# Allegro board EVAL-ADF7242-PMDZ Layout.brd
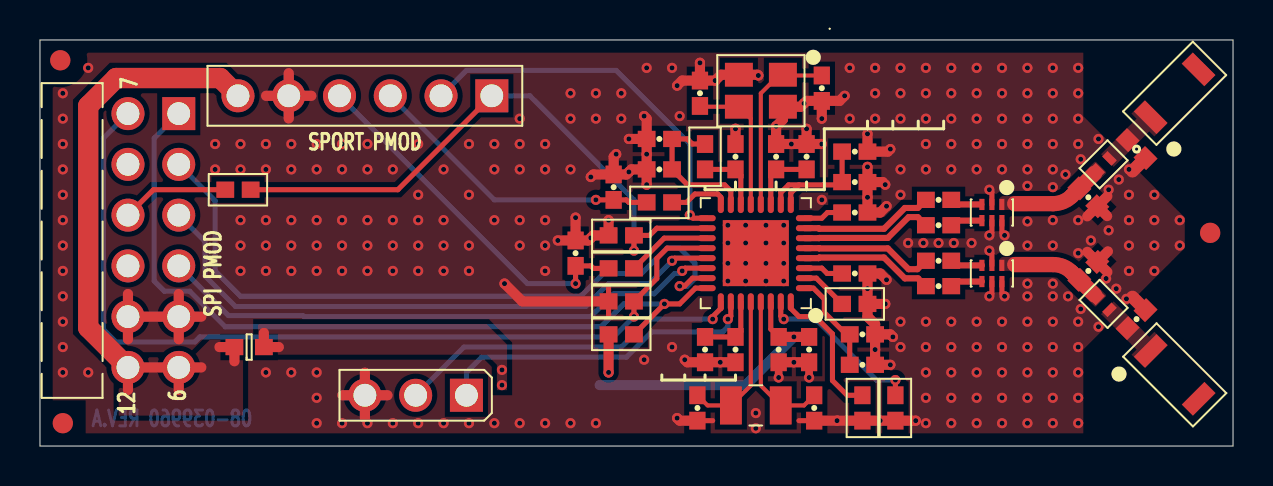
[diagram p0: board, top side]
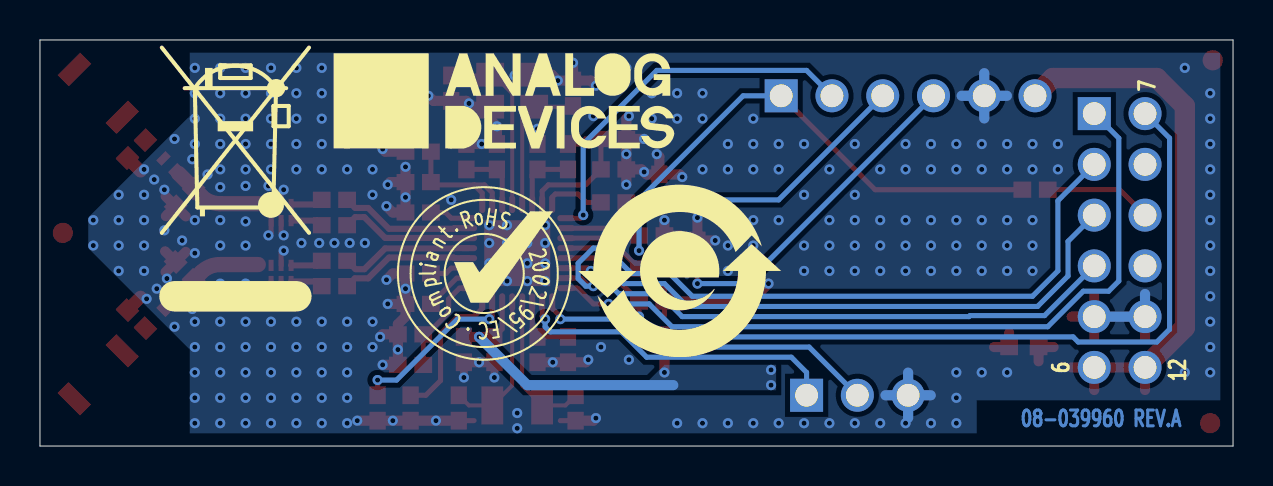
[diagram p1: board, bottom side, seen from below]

Outline 59.69 x 20.32 mm; copper layers: TOP, L2_GND, L3_GND, BOTTOM. Coordinates in mm from the lower left corner of the outline.
Outline path: 0,20.32 0,0 59.69,0 59.69,20.32 0,20.32

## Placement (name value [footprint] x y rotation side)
C1  0.22uF  [C0402]  41.15 4.06 180 top
C2  27pF  [C0402]  41.15 5.59 180 top
C3  27pF  [C0402]  40.77 8.64 180 top
C4  10000pF  [C0402]  44.96 8 180 top
C5  0.1UF  [C0402]  28.7 12.95 270 top
C6  10000pF  [C0402]  44.96 9.27 180 top
C7  10000pF  [C0402]  44.96 11.05 180 top
C8  10000pF  [C0402]  44.96 12.32 180 top
C9  0.1UF  [C0402]  26.8 9.65 270 top
C10  18pF  [C0402]  39.12 17.91 90 top
C11  1pF  [C0402]  54.86 14.86 135 top
C12  27pF  [C0402]  40.77 11.68 180 top
C13  27pF  [C0402]  34.8 4.83 270 top
C14  27pF  [C0402]  40.77 13.21 180 top
C15  0.22uF  [C0402]  40.77 14.73 180 top
C16  1pF  [C0402]  54.86 6.35 225 top
C17  27pF  [C0402]  36.83 14.48 270 top
C18  0.22uF  [C0402]  38.35 14.48 270 top
C19  1pF  [C0402]  52.45 12.45 135 top
C20  18pF  [C0402]  33.02 17.65 270 top
C21  27pF  [C0402]  34.8 14.48 270 top
C22  0.1UF  [C0402]  30.99 15.37 0 top
C23  27pF  [C0402]  30.99 13.84 0 top
C24  0.1UF  [C0402]  36.96 4.83 90 top
C25  27pF  [C0402]  38.48 4.83 90 top
C26  8pF  [C0402]  38.73 1.91 90 top
C27  8pF  [C0402]  32.89 1.91 90 top
C28  0.1UF  [C0402]  33.27 4.83 270 top
C29  1pF  [C0402]  52.45 8.76 225 top
E1  600OHMS  [L0603]  10.46 4.95 0 top
FL1  2400-2500MEGHZ  [FLSML126W63H55]  56.77 3.56 315 top
FL2  2400-2500MEGHZ  [FLSML126W63H55]  56.77 17.65 45 top
L1  2.4nH  [L0402-2]  53.21 7.11 135 top
L2  2.4nH  [L0402-2]  53.21 14.1 225 top
NOREF  -  []  -219.71 -146.05 0 top
NOREF#2  -  []  119.38 340.74 0 top
NOREF#3  -  []  32.59 36.5 0 top
NOREF#4  -  [unnamed#2]  1.14 1.14 0 top
NOREF#5  -  []  0 0 0 top
NOREF#6  -  []  0 20.32 270 top
NOREF#7  -  []  161.8 51.82 0 top
NOREF#8  -  []  1.14 1.14 0 top
NOREF#9  -  []  0 20.32 0 top
NOREF#10  -  []  -88.27 331.85 0 top
NOREF#11  -  []  33.76 58.18 0 top
NOREF#12  -  [unnamed#2]  58.55 10.67 0 top
NOREF#13  -  []  0 20.32 0 top
NOREF#14  -  []  -219.71 -146.05 0 top
NOREF#15  -  []  -219.71 -146.05 0 top
NOREF#16  -  []  0 0 0 top
NOREF#17  -  []  59.69 20.32 180 top
NOREF#18  -  []  59.69 0 90 top
NOREF#19  -  []  0 0 0 top
NOREF#20  -  []  1.14 1.14 0 top
NOREF#21  -  []  59.69 0 90 top
NOREF#22  -  [unnamed#2]  1.02 19.3 0 top
NOREF#23  -  []  59.69 0 0 top
NOREF#24  -  []  36.45 17.27 180 bottom
NOREF#25  -  []  27.69 8.76 180 bottom
NOREF#26  -  []  37.47 8.64 180 bottom
NOREF#27  -  []  40.64 23.62 180 bottom
P1  TSW-106-25-F-D-RA  [CNHDRRA2X6H240]  6.94 16.63 270 top
P2  TSW-106-09-G-S  [CNHDR1X6H330]  22.61 17.53 180 top
P3  MOLEX22-03-2031  [CNMOLEX22-03-2031]  21.34 2.54 180 top
R1  100K  [R0402]  42.8 1.91 90 top
R2  100K  [R0402]  41.15 1.91 90 top
R3  27K  [R0402]  40.77 7.11 180 top
R4  0  [R0402]  33.27 14.48 90 top
R5  100K  [R0402]  29.08 5.59 180 top
R6  0  [R0402]  9.91 12.83 0 top
R7  100K  [R0402]  29.08 7.24 0 top
R8  100K  [R0402]  29.08 10.54 0 top
R9  0  [R0402]  29.08 8.89 180 top
R10  0  [R0402]  30.99 12.19 180 top
U1  ADF7242BCPZ  [QFN32_5X5_PAD3_3X3_3]  35.81 9.65 90 top
U2  2400-2500MEGHZ  [FL0603-6P]  47.62 11.68 180 top
U3  2400-2500MEGHZ  [FL0603-6P]  47.62 8.64 180 top
Y1  26.000MEGHZ  [XTALNX3225]  36.07 17.78 180 top
Y2  32.768KHz  [YSML126W59H35]  35.81 2.03 180 top

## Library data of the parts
C1 C15 C18 = CAP: Tolerance: 10; User Part Number: UPN; alternate symbols: (C0402H22_ALT,C0201-2,C0402_A,C0402_ALT,C0402L_ALT,C0603L_ALT); part number: CAP_SM-0.22UF,10V,10,E011012,C0402; tolerance: 10
C2 C3 C12-C14 C17 C21 C23 C25 = CAP: Tolerance: 5; User Part Number: UPN; alternate symbols: (C0402H22_ALT,C0201-2,C0402_A,C0402_ALT,C0402L_ALT,C0603L_ALT); part number: CAP_SM-27PF,50V,5,E006647,C0402; tolerance: 5
C4 C6-C8 = CAP: Tolerance: 10; User Part Number: UPN; alternate symbols: (C0402H22_ALT,C0201-2,C0402_A,C0402_ALT,C0402L_ALT,C0603L_ALT); part number: CAP_SM-10000PF,50V,10,E021852,C0402; tolerance: 10
C5 C9 C22 C24 C28 = CAP: Tolerance: 10; User Part Number: UPN; alternate symbols: (C0402H22_ALT,C0201-2,C0402_A,C0402_ALT,C0402L_ALT,C0603L_ALT); part number: CAP_SM-0.1UF,16V,10,E007200,C0402; tolerance: 10
C10 C20 = CAP: Tolerance: 5; User Part Number: UPN; alternate symbols: (C0402H22_ALT,C0201-2,C0402_A,C0402_ALT,C0402L_ALT,C0603L_ALT); part number: CAP_SM-18PF,50V,5,E007476,C0402; tolerance: 5
C11 C16 C19 C29 = CAP: Tolerance: 0.25pF; User Part Number: UPN; alternate symbols: (C0402H22_ALT,C0201-2,C0402_A,C0402_ALT,C0402L_ALT,C0603L_ALT); part number: CAP_SM-1PF,50V,0.25PF,E022519,C0402; tolerance: 0.25pF
C26 C27 = CAP: Tolerance: +/-0.5pF; User Part Number: UPN; alternate symbols: (C0402H22_ALT,C0201-2,C0402_A,C0402_ALT,C0402L_ALT,C0603L_ALT); part number: CAP_SM-8PF,50V,+/-0.5PF,E012604,C0402; tolerance: +/-0.5pF
E1 = FERRITE: Tolerance: N/A; User Part Number: UPN; alternate symbols: (L1210H59_ALT); part number: FERRITE_SM-600OHMS,N/A,E007179,L0603; tolerance: N/A
FL1 FL2 = FLTRRF2P: User Part Number: UPN; part number: FLTRRF2P_SM-2400-2500MEGHZ,E021871,FLSML126W63H55
L1 L2 = IND: Tolerance: 2; User Part Number: UPN; alternate symbols: (L0402-2,L0603_ALT,L1008L_ALT); part number: IND_SM-2.4NH,2,E020887,L0402-2; tolerance: 2
P1 = CN12P_V3: User Part Number: UPN; part number: CN12P_V3_TH-TSW-106-25-F-D-RA,E018495,CNHDRRA2X6H240
P2 = CN6P: User Part Number: UPN; part number: CN6P_TH-TSW-106-09-G-S,E020774,CNHDR1X6H330
P3 = CN3P: User Part Number: UPN; part number: CN3P_TH-MOLEX22-03-2031,E000811,CNMOLEX22-03-2031
R1 R2 R5 R7 R8 = RES: Tolerance: 1; User Part Number: UPN; alternate symbols: (RRAD984L1500W75H520LD32;TO220H590_ALT;R0402_A;R0603_A,R0402_ALT,R0402L_ALT); part number: RES_SM-100K,E003796,1/16W,1,R0402; tolerance: 1
R3 = RES: Tolerance: 1; User Part Number: UPN; alternate symbols: (RRAD984L1500W75H520LD32;TO220H590_ALT;R0402_A;R0603_A,R0402_ALT,R0402L_ALT); part number: RES_SM-27K,E007442,1/16W,1,R0402; tolerance: 1
R4 R6 R9 R10 = RES: Tolerance: 1; User Part Number: UPN; alternate symbols: (RRAD984L1500W75H520LD32;TO220H590_ALT;R0402_A;R0603_A,R0402_ALT,R0402L_ALT); part number: RES_SM-0,E010661,1/16W,1,R0402; tolerance: 1
U1 = ADF7242: User Part Number: UPN; part number: ADF7242_SM-ADF7242BCPZ,E020886,QFN32_5X5_PAD3_3X3_3
U2 U3 = FLTRBALUN6P: User Part Number: UPN; part number: FLTRBALUN6P_SM-2400-2500MEGHZ,E020950,FL0603-6P
Y1 = XTALNX3225: User Part Number: UPN; part number: XTALNX3225_SM-26.000MEGHZ,E014734,XTALNX3225
Y2 = XTAL: User Part Number: UPN; Tolerance: 20PPM; part number: XTAL_SM-32.768KHZ,E019185,YSML126W59H35; tolerance: 20PPM

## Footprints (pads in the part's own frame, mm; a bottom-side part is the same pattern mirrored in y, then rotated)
C0402
  rect 0.889x0.813 smd: 1(-0.635,0) 2(0.635,0)
CNHDR1X6H330
  rect 1.651x1.651 hole 1.143: 1(0,0)
  round 1.651 hole 1.143: 2(2.54,0) 3(5.08,0) 4(7.62,0) 5(10.16,0) 6(12.7,0)
CNHDRRA2X6H240
  rect 1.651x1.651 hole 1.143: 1(0,0)
  round 1.651 hole 1.143: 2(2.54,0) 3(5.08,0) 4(7.62,0) 5(10.16,0) 6(12.7,0) 7(0,-2.54) 8(2.54,-2.54) 9(5.08,-2.54) 10(7.62,-2.54) 11(10.16,-2.54) 12(12.7,-2.54)
CNMOLEX22-03-2031
  rect 1.651x1.651 hole 1.143: 1(0,0)
  round 1.651 hole 1.143: 2(2.54,0) 3(5.08,0)
FL0603-6P
  rect 0.254x0.559 smd: 1(-0.5,-0.404) 2(0,-0.404) 3(0.5,-0.404) 4(0.5,0.404) 5(0,0.404) 6(-0.5,0.404)
FLSML126W63H55
  rect 0.787x1.6 smd: 1(-1.694,0) 2(1.694,0)
L0402-2
  rect 0.381x0.66 smd: 1(-0.419,0) 2(0.419,0)
L0603
  rect 0.889x0.813 smd: 1(-0.737,0) 2(0.737,0)
QFN32_5X5_PAD3_3X3_3
  oval 0.305x0.889 smd: 1(-1.75,-2.45) 2(-1.25,-2.45) 3(-0.75,-2.45) 4(-0.25,-2.45) 5(0.25,-2.45) 6(0.75,-2.45) 7(1.25,-2.45) 8(1.75,-2.45) 17(1.75,2.45) 18(1.25,2.45) 19(0.75,2.45) 20(0.25,2.45) 21(-0.25,2.45) 22(-0.75,2.45) 23(-1.25,2.45) 24(-1.75,2.45)
  oval 0.889x0.305 smd: 9(2.45,-1.75) 10(2.45,-1.25) 11(2.45,-0.75) 12(2.45,-0.25) 13(2.45,0.25) 14(2.45,0.75) 15(2.45,1.25) 16(2.45,1.75) 25(-2.45,1.75) 26(-2.45,1.25) 27(-2.45,0.75) 28(-2.45,0.25) 29(-2.45,-0.25) 30(-2.45,-0.75) 31(-2.45,-1.25) 32(-2.45,-1.75)
  rect 3.302x3.302 smd: PAD(0,0)
R0402
  rect 0.889x0.813 smd: 1(-0.635,0) 2(0.635,0)
unnamed#2
  round 1.016 smd: (0,0)
XTALNX3225
  rect 1.397x1.194 smd: 1(-1.1,-0.8) 2(1.1,-0.8) 3(1.1,0.8) 4(-1.1,0.8)
YSML126W59H35
  rect 1.092x1.905 smd: 1(-1.246,0) 2(1.246,0)

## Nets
DGND: C1.1(N1) C2.1(N1) C3.1(N1) C5.1(N1) C9.1(N1) C10.1(N1) C11.1(N1) C12.1(N1) C13.2(N2) C14.1(N1) C15.1(N1) C16.1(N1) C17.1(N1) C18.1(N1) C19.1(N1) C20.1(N1) C21.1(N1) C22.1(N1) C23.1(N1) C24.1(N1) C25.1(N1) C26.1(N1) C27.1(N1) C28.2(N2) C29.1(N1) P1.5(GND1) P1.11(GND2) P2.5(N5) P3.3(N3) R1.1(N1) R2.1(N1) R3.1(N1) R7.1(N1) R8.1(N1) U1.PAD(EPAD) U2.2(GND1) U2.5(GND2) U2.6(GND3) U3.2(GND1) U3.5(GND2) U3.6(GND3) Y1.2(CASE1) Y1.4(CASE2)
DVDD: E1.1(N1) P1.6(VCC1) P1.12(VCC2) P2.6(N6)
CS: P1.1(P1) R5.1(N1) U1.24(CS_N)
DR: C5.2(N2) P2.3(N3) R10.2(N2)
DT: P2.2(N2) U1.17(DT_GP1)
IRQ1IN: P1.7(P7) R7.2(N2) U1.20(IRQ1_GP4)
IRQ2_TRFS: P2.1(N1) R6.2(N2) R8.2(N2) U1.18(IRQ2_TRFS_GP2)
MISO: P1.3(P3) U1.21(MISO)
MOSI: P1.2(P2) U1.23(MOSI)
RFVDD: C24.2(N2) C25.2(N2) E1.2(N2) R5.2(N2) U1.30(VDD_BAT)
RXEN: P3.1(N1) U1.26(RXEN_GP6)
SCLK: P1.4(P4) U1.22(SCLK)
SPORT_CLK: C9.2(N2) P2.4(N4) R9.2(N2)
TXEN: P3.2(N2) U1.25(TXEN_GP5)
UNNAMED_4_ADF7242_I75_CREGDIG1: C13.1(N1) C28.1(N1) U1.27(CREGDIG1)
UNNAMED_4_ADF7242_I75_CREGDIG2: C22.2(N2) C23.2(N2) R4.2(N2) U1.15(CREGDIG2)
UNNAMED_4_ADF7242_I75_CREGRF1: C1.2(N2) C2.2(N2) U1.1(CREGRF1)
UNNAMED_4_ADF7242_I75_CREGRF2: C3.2(N2) U1.3(CREGRF2)
UNNAMED_4_ADF7242_I75_CREGRF3: C12.2(N2) U1.8(CREGRF3)
UNNAMED_4_ADF7242_I75_CREGSYNTH: C17.2(N2) C18.2(N2) U1.11(CREGSYNTH)
UNNAMED_4_ADF7242_I75_CREGVCO: C14.2(N2) C15.2(N2) U1.9(CREGVCO) U1.10(VCOGUARD)
UNNAMED_4_ADF7242_I75_DGUARD: C21.2(N2) R4.1(N1) U1.14(DGUARD)
UNNAMED_4_ADF7242_I75_DRGP0: R10.1(N1) U1.16(DR_GP0)
UNNAMED_4_ADF7242_I75_PABIAOPAT: R2.2(N2) U1.32(PABIAOP_ATB4)
UNNAMED_4_ADF7242_I75_PAVSUPATB: R1.2(N2) U1.31(PAVSUP_ATB3)
UNNAMED_4_ADF7242_I75_RBIAS: R3.2(N2) U1.2(RBIAS)
UNNAMED_4_ADF7242_I75_RFIO1N: C6.2(N2) U1.5(RFIO1N)
UNNAMED_4_ADF7242_I75_RFIO1P: C4.2(N2) U1.4(RFIO1P)
UNNAMED_4_ADF7242_I75_RFIO2N: C8.2(N2) U1.7(RFIO2N)
UNNAMED_4_ADF7242_I75_RFIO2P: C7.2(N2) U1.6(RFIO2P)
UNNAMED_4_ADF7242_I75_TRCLKCKOG: R9.1(N1) U1.19(TRCLK_CKO_GP3)
UNNAMED_4_ADF7242_I75_XOSC26N: C20.2(N2) U1.13(XOSC26N) Y1.3(N2)
UNNAMED_4_ADF7242_I75_XOSC26P: C10.2(N2) U1.12(XOSC26P) Y1.1(N1)
UNNAMED_4_ADF7242_I75_XOSC32KNA: C26.2(N2) U1.29(XOSC32KN_ATB2) Y2.1(N1)
UNNAMED_4_ADF7242_I75_XOSC32KPG: C27.2(N2) U1.28(XOSC32KP_GP7_ATB1) Y2.2(N2)
UNNAMED_4_CAP_I13_N1: C8.1(N1) U2.3(BALANCED PORT1)
UNNAMED_4_CAP_I97_N1: C7.1(N1) U2.4(BALANCED PORT2)
UNNAMED_4_CAP_I98_N1: C6.1(N1) U3.3(BALANCED PORT1)
UNNAMED_4_CAP_I99_N1: C4.1(N1) U3.4(BALANCED PORT2)
UNNAMED_4_CAP_I134_N2: C19.2(N2) L2.2(N2) U2.1(UNBALANCED PORT)
UNNAMED_4_CAP_I144_N2: C11.2(N2) FL2.1(FEEDING_POINT) L2.1(N1)
UNNAMED_4_CAP_I145_N2: C16.2(N2) FL1.1(FEEDING_POINT) L1.1(N1)
UNNAMED_4_CAP_I146_N2: C29.2(N2) L1.2(N2) U3.1(UNBALANCED PORT)
UNNAMED_4_CN12PV3_I76_P9: P1.9(P9) R6.1(N1)

Pads without a net: FL1 2; FL2 2; P1 8 10

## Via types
v1: diameter 0.508, hole 0.254, TOP to BOTTOM, 314 vias

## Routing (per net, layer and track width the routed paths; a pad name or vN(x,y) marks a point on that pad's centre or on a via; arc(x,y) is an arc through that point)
DGND: length 140.9
  TOP w0.254: 28.45,7.95 R7.1 28.45,6.53 ; U2.5 47.62,10.67 v1(47.5,10.54) ; 53.43,11.47 53.39,11.51 ; C26.1 37.97,1.27 ; C27.1 33.66,1.27 ; U3.2 47.62,9.65 v1(47.5,9.78) ; v1(47.5,12.83) 47.62,12.7 U2.2 ; U2.6 48.13,10.68 v1(48.26,10.54) ; v1(47.5,7.49) 47.62,7.62 U3.5 ; U3.6 48.13,7.63 v1(48.26,7.49)
  TOP w0.381: C24.1 v1(36.96,3.43) ; C25.1 v1(38.48,3.43)
  TOP w0.508: C9.1 27.43,10.29 v1(27.56,10.41) 27.69,10.54 R8.1 v1(28.45,11.3) ; C9.1 v1(25.91,10.29) ; C9.1 v1(26.8,11.43) ; 16.26,2.54 15.13,2.54 ; 16.26,2.54 16.26,3.67 ; 16.26,2.54 16.26,1.41 ; 16.26,2.54 17.39,2.54 ; C14.1 42.16,13.21 v1(42.29,13.08) ; C14.1 v1(41.4,12.45) C12.1 42.04,11.68 v1(42.35,12) ; C14.1 v1(41.4,13.97) ; 39.12,17.27 38.35,17.27 v1(38.23,17.14) 38.06,16.98 Y1.4 37.17,16.34 v1(36.83,16) C17.1 v1(37.59,15.11) C18.1 ; 39.12,17.27 v1(39.12,16.38) ; 39.12,17.27 40.01,17.27 v1(40.26,17.53) ; 53.39,11.51 C19.1 ; C19.1 52.4,11.49 ; C19.1 53.4,12.5 ; v1(27.56,13.46) 27.69,13.59 C5.1 ; R3.1 v1(42.29,7.11) ; R3.1 v1(41.4,7.87) C3.1 42.04,8.64 v1(42.35,8.32) ; R3.1 41.4,6.48 41.78,6.1 C2.1 ; C2.1 v1(41.78,4.83) C1.1 v1(42.55,4.06) ; C2.1 42.55,5.59 v1(42.67,5.46) ; C5.1 28.7,14.48 v1(28.83,14.61) ; C5.1 29.34,13.59 v1(29.46,13.72) 29.59,13.84 C23.1 ; P2.5 12.45,16.4 ; P2.5 11.32,17.53 ; P2.5 12.45,18.66 ; P2.5 13.58,17.53 ; C29.1 52.4,9.72 ; C29.1 53.4,8.71 ; C29.1 53.43,9.74 ; v1(32.26,4.32) 32.38,4.19 C28.2 v1(34.04,4.19) C13.2 ; v1(31.88,1.4) 32,1.27 C27.1 ; 33.02,18.29 32.13,18.29 v1(31.88,18.03) ; 33.02,18.29 v1(33.78,18.29) 34.07,18.58 Y1.2 35.9,18.58 v1(35.94,18.54) ; 33.02,18.29 v1(33.02,19.18) ; P1.5 8.07,6.47 ; P1.5 6.94,5.34 ; P1.5 P1.11 ; P1.5 6.94,7.61 ; C18.1 v1(38.35,15.88) ; C18.1 v1(39.12,15.11) ; C23.1 v1(30.35,13.08) ; C23.1 v1(30.35,14.61) C22.1 ; P1.11 4.4,5.34 ; P1.11 4.4,7.61 ; C24.1 v1(37.72,4.19) C25.1 ; C22.1 v1(29.46,15.37) ; C22.1 30.35,16.38 v1(30.23,16.51) ; v1(42.55,14.86) 42.42,14.73 C15.1 v1(41.4,15.62) ; v1(43.81,1.27) R1.1 v1(42.04,1.27) R2.1 v1(39.88,1.27) C26.1 ; v1(23.24,8.13) 24.13,7.24 R7.1 ; C21.1 v1(34.8,15.88)
  TOP w0.635: 54.66,7.45 C16.1 ; C11.1 54.66,13.75
  L2_GND w0.508: P1.5 6.94,7.61 ; P1.5 6.94,5.34 ; P1.5 8.07,6.47 ; P1.5 P1.11 ; 16.26,2.54 17.39,2.54 ; 16.26,2.54 16.26,3.67 ; 16.26,2.54 16.26,1.41 ; 16.26,2.54 15.13,2.54 ; P1.11 3.27,6.47 ; P1.11 4.4,7.61 ; P1.11 4.4,5.34 ; P2.5 12.45,18.66 ; P2.5 11.32,17.53 ; P2.5 12.45,16.4 ; P2.5 13.58,17.53
  L3_GND w0.508: P2.5 13.58,17.53 ; P2.5 12.45,18.66 ; P2.5 12.45,16.4 ; P2.5 11.32,17.53 ; P1.5 8.07,6.47 ; P1.5 6.94,5.34 ; P1.5 P1.11 ; P1.5 6.94,7.61 ; P1.11 4.4,5.34 ; P1.11 3.27,6.47 ; P1.11 4.4,7.61 ; 16.26,2.54 16.26,1.41 ; 16.26,2.54 15.13,2.54 ; 16.26,2.54 16.26,3.67 ; 16.26,2.54 17.39,2.54
  BOTTOM w0.508: P2.5 11.32,17.53 ; P2.5 12.45,16.4 ; P2.5 13.58,17.53 ; P2.5 12.45,18.66 ; 16.26,2.54 16.26,3.67 ; 16.26,2.54 15.13,2.54 ; 16.26,2.54 17.39,2.54 ; 16.26,2.54 16.26,1.41 ; 4.4,7.61 P1.11 P1.5
  vias: v1(1.14,17.65) v1(1.14,16.38) v1(1.14,15.11) v1(1.14,13.84) v1(1.14,12.57) v1(1.14,11.3) v1(1.14,10.03) v1(1.14,8.76) v1(1.14,7.49) v1(1.14,6.22) v1(1.14,4.95) v1(1.14,3.68) v1(2.41,18.92) v1(2.41,3.68) v1(8.76,15.11) v1(8.76,13.84) v1(10.03,15.11) v1(10.03,13.84) v1(10.03,11.3) v1(10.03,10.03) v1(10.03,8.76) v1(11.3,15.11) v1(11.3,13.84) v1(11.3,11.3) v1(11.3,10.03) v1(11.3,8.76) v1(11.3,3.68) v1(12.57,15.11) v1(12.57,13.84) v1(12.57,11.3) v1(12.57,10.03) v1(12.57,8.76) v1(12.57,3.68) v1(13.84,15.11) v1(13.84,13.84) v1(13.84,11.3) v1(13.84,10.03) v1(13.84,8.76) v1(13.84,3.68) v1(13.84,2.41) v1(13.84,1.14) v1(15.11,15.11) v1(15.11,13.84) v1(15.11,11.3) v1(15.11,10.03) v1(15.11,8.76) v1(15.11,1.14) v1(16.38,15.11) v1(16.38,13.84) v1(16.38,11.3) v1(16.38,10.03) v1(16.38,8.76) v1(16.38,1.14) v1(17.65,13.84) v1(17.65,11.3) v1(17.65,10.03) v1(17.65,8.76) v1(17.65,1.14) v1(18.92,15.11) v1(18.92,12.57) v1(18.92,11.3) v1(18.92,10.03) v1(18.92,8.76) v1(18.92,1.14) v1(20.19,13.84) v1(20.19,11.3) v1(20.19,10.03) v1(20.19,8.76) v1(20.19,1.14) v1(21.46,15.11) v1(21.46,12.57) v1(21.46,10.03) v1(21.46,8.76) v1(21.46,1.14) v1(22.73,15.11) v1(22.73,13.84) v1(22.73,11.3) v1(22.73,1.14) v1(24,16.38) v1(24,15.11) v1(24,13.84) v1(24,11.3) v1(24,10.03) v1(24,1.14) v1(25.27,15.11) v1(25.27,13.84) v1(25.27,11.3) v1(25.27,10.03) v1(25.27,8.76) v1(25.27,1.14) v1(26.54,17.65) v1(26.54,16.38) v1(26.54,13.84) v1(26.54,1.14) v1(27.81,17.65) v1(27.81,16.38) v1(27.81,1.14) v1(29.08,17.65) v1(29.08,16.38) v1(30.23,4.32) v1(30.35,18.92) v1(31.62,18.92) v1(31.62,4.95) v1(32,16.51) v1(34.42,11.05) v1(34.42,10.16) v1(34.42,9.14) v1(34.42,8.26) v1(35.31,11.05) v1(35.31,10.16) v1(35.31,9.14) v1(35.31,8.26) v1(35.81,1.65) v1(35.81,0.89) v1(36.32,11.05) v1(36.32,10.16) v1(36.32,9.14) v1(36.32,8.26) v1(37.21,11.05) v1(37.21,10.16) v1(37.21,9.14) v1(37.21,8.26) v1(39.12,12.32) v1(40.51,18.92) v1(40.51,16.38) v1(41.78,18.92) v1(41.78,17.65) v1(41.78,16.38) v1(43.05,18.92) v1(43.05,17.65) v1(43.05,16.38) v1(43.05,13.84) v1(43.05,12.57) v1(43.05,6.22) v1(43.05,4.95) v1(43.43,10.16) v1(44.2,10.16) v1(44.32,18.92) v1(44.32,17.65) v1(44.32,16.38) v1(44.32,15.11) v1(44.32,13.84) v1(44.32,6.22) v1(44.32,4.95) v1(44.32,3.68) v1(44.32,2.41) v1(44.32,1.14) v1(44.96,10.16) v1(45.59,18.92) v1(45.59,17.65) v1(45.59,16.38) v1(45.59,15.11) v1(45.59,13.84) v1(45.59,6.22) v1(45.59,4.95) v1(45.59,3.68) v1(45.59,2.41) v1(45.59,1.14) v1(45.72,10.16) v1(46.61,10.16) v1(46.86,18.92) v1(46.86,17.65) v1(46.86,16.38) v1(46.86,15.11) v1(46.86,13.84) v1(46.86,6.22) v1(46.86,4.95) v1(46.86,3.68) v1(46.86,2.41) v1(46.86,1.14) v1(48.13,18.92) v1(48.13,17.65) v1(48.13,16.38) v1(48.13,15.11) v1(48.13,13.84) v1(48.13,6.22) v1(48.13,4.95) v1(48.13,3.68) v1(48.13,2.41) v1(48.13,1.14) v1(48.26,13.02) v1(49.4,18.92) v1(49.4,17.65) v1(49.4,16.38) v1(49.4,15.11) v1(49.4,13.84) v1(49.4,13.02) v1(49.4,11.24) v1(49.4,10.03) v1(49.4,8.13) v1(49.4,7.49) v1(49.4,6.22) v1(49.4,4.95) v1(49.4,3.68) v1(49.4,2.41) v1(49.4,1.14) v1(50.67,18.92) v1(50.67,17.65) v1(50.67,16.38) v1(50.67,15.11) v1(50.67,13.84) v1(50.67,12.95) v1(50.67,11.3) v1(50.67,10.03) v1(50.67,8.13) v1(50.67,7.49) v1(50.67,6.22) v1(50.67,4.95) v1(50.67,3.68) v1(50.67,2.41) v1(50.67,1.14) v1(51.31,13.59) v1(51.44,7.49) v1(51.94,18.92) v1(51.94,17.65) v1(51.94,16.38) v1(51.94,15.11) v1(51.94,11.3) v1(51.94,9.65) v1(51.94,6.22) v1(51.94,4.95) v1(51.94,3.68) v1(51.94,2.41) v1(51.94,1.14) v1(52.07,14.35) v1(52.07,6.86) v1(52.58,10.29) v1(52.96,15.37) v1(52.96,5.97) v1(53.34,8.38) v1(53.47,12.83) v1(53.47,10.79) v1(53.85,7.87) v1(53.98,13.34) v1(54.36,7.37) v1(54.48,13.84) v1(54.48,12.57) v1(54.48,11.3) v1(54.48,10.03) v1(54.48,8.76) v1(55.75,12.57) v1(55.75,11.3) v1(55.75,10.03) v1(55.75,8.76) v1(57.02,11.3) v1(57.02,10.03)
DVDD: length 29.7
  TOP w0.508: 8.98,4.95 E1.1 9.73,4.24 ; 4.4,2.8 P1.12 P1.6 ; P1.6 8.07,3.93 ; P1.6 6.94,2.8
  TOP w1.016: P2.6 9.02,18.41 3.81,18.41 2.41,17.02 2.41,5.92 P1.12
CS: length 40.4
  TOP w0.254: R5.1 v1(31.24,7.11) 32,7.11 32.79,7.9 U1.24
  BOTTOM w0.254: P1.1 5.71,15.41 5.71,8.26 6.22,7.75 7.49,7.75 9.27,5.97 28.07,5.97 29.21,7.11 v1(31.24,7.11)
DR: length 15
  TOP w0.254: R10.2 29.46,12.19 29.34,12.32 C5.2 v1(27.81,12.32)
  BOTTOM w0.254: P2.3 22.73,12.32 v1(27.81,12.32)
DT: length 19
  TOP w0.254: v1(32.51,11.56) 32.67,11.4 U1.17
  BOTTOM w0.254: v1(32.51,11.56) 32.51,15.11 28.83,18.8 21.34,18.8 P2.2
IRQ1IN: length 44.7
  TOP w0.254: U1.20 31.38,9.9 30.86,9.39 30.86,8.38 R7.2 v1(29.72,6.48)
  BOTTOM w0.254: v1(29.72,6.48) 28.7,5.46 8,5.46 7.75,5.21 3.81,5.21 3.17,5.84 3.17,15.41 P1.7
IRQ2_TRFS: length 30.4
  TOP w0.254: P2.1 17.91,12.83 R6.2 ; v1(29.72,9.78) R8.2 30.5,10.54 30.86,10.9 U1.18
  BOTTOM w0.254: v1(29.72,9.78) 29.72,12.32 24.51,17.53 P2.1
MISO: length 30.3
  TOP w0.254: U1.21 31.75,9.4 v1(31.62,9.27)
  BOTTOM w0.254: P1.3 8.26,10.24 8.26,8.51 9.78,6.98 27.3,6.98 28.45,8.13 30.48,8.13 v1(31.62,9.27)
MOSI: length 35.1
  TOP w0.254: U1.23 32.65,8.4 32.25,8 v1(32,8)
  BOTTOM w0.254: v1(32,8) 32.38,8 32.77,8.38 32.77,9.14 32,9.91 31.37,9.91 30.1,8.64 28.19,8.64 27.05,7.49 10.03,7.49 8.76,8.76 8.76,12.27 P1.2
RFVDD: length 17.5
  TOP w0.254: U1.30 36.56,5.85 C24.2
  TOP w0.508: C24.2 v1(37.72,5.46) C25.2 ; 11.2,5.66 E1.2 11.95,4.95 ; R5.2 v1(28.45,3.68)
  BOTTOM w0.508: 28,3.05 35.31,3.05 v1(37.72,5.46)
  vias: v1(23.11,3.81) v1(23.11,3.05)
RXEN: length 16.5
  TOP w0.254: U1.26 34.56,6.5 v1(34.42,6.35)
  BOTTOM w0.254: v1(34.42,6.35) 34.42,5.97 34.16,5.71 30.61,5.71 29.34,4.45 22.1,4.45 21.34,3.68 P3.1
SCLK: length 28.5
  TOP w0.254: U1.22 32.27,8.9 v1(32.13,8.76)
  BOTTOM w0.254: P1.4 9.43,6.53 13.16,6.53 13.21,6.48 27.56,6.48 28.7,7.62 30.73,7.62 31.75,8.64 32,8.64 v1(32.13,8.76)
SPORT_CLK: length 18.3
  TOP w0.254: R9.2 27.69,8.89 27.56,9.02 C9.2 v1(26.8,8.13)
  BOTTOM w0.254: v1(26.8,8.13) 24.38,8.13 P2.4
TXEN: length 17.5
  TOP w0.254: v1(33.66,6.35) 33.66,6.48 34.06,6.89 U1.25
  BOTTOM w0.254: 18.8,2.54 21.21,4.95 29.08,4.95 30.48,6.35 v1(33.66,6.35)
UNNAMED_4_ADF7242_I75_CREGDIG1: length 3.4
  TOP w0.254: C28.1 C13.1 35.06,5.73 U1.27
UNNAMED_4_ADF7242_I75_CREGDIG2: length 7.3
  TOP w0.254: U1.15 34.56,12.76 34.25,13.07 32.4,13.07 C23.2 C22.2 32.38,15.37 32.64,15.11 R4.2
UNNAMED_4_ADF7242_I75_CREGRF1: length 5.1
  TOP w0.254: U1.1 38.7,7.9 39.24,7.35 39.24,6.68 40.34,5.59 C2.2 C1.2
UNNAMED_4_ADF7242_I75_CREGRF2: length 2
  TOP w0.254: 40.13,8.64 39.38,8.64 39.12,8.9 U1.3
UNNAMED_4_ADF7242_I75_CREGRF3: length 2
  TOP w0.254: 40.13,11.68 39.4,11.68 39.12,11.4 U1.8
UNNAMED_4_ADF7242_I75_CREGSYNTH: length 3.4
  TOP w0.254: C18.2 C17.2 36.56,13.58 U1.11
UNNAMED_4_ADF7242_I75_CREGVCO: length 6.5
  TOP w0.254: 37.97,13.07 39.99,13.07 40.13,13.21 40.13,14.73 ; 37.97,13.07 37.45,13.07 37.06,12.68 U1.10 ; 37.97,13.07 37.56,12.66 U1.9
UNNAMED_4_ADF7242_I75_DGUARD: length 3.4
  TOP w0.254: R4.1 C21.2 35.06,13.58 U1.14
UNNAMED_4_ADF7242_I75_DRGP0: length 3
  TOP w0.254: U1.16 34.06,12.46 33.91,12.61 32.77,12.61 32.35,12.19 R10.1
UNNAMED_4_ADF7242_I75_PABIAOPAT: length 7.1
  TOP w0.254: U1.32 37.56,6.89 37.97,6.48 38.78,6.48 39.65,5.61 39.65,3.28 40.39,2.54 R2.2
UNNAMED_4_ADF7242_I75_PAVSUPATB: length 8.5
  TOP w0.254: R1.2 v1(42.8,3.3) ; U1.31 37.06,6.5 v1(37.21,6.35)
  BOTTOM w0.254: v1(42.8,3.3) 41.85,3.3 38.8,6.35 v1(37.21,6.35)
UNNAMED_4_ADF7242_I75_RBIAS: length 2.4
  TOP w0.254: 40.13,7.11 38.84,8.4 U1.2
UNNAMED_4_ADF7242_I75_RFIO1N: length 6.7
  TOP w0.305: C6.2 43.9,8.85 43.46,8.85 42.42,9.89 38.99,9.89 38.98,9.9 U1.5
UNNAMED_4_ADF7242_I75_RFIO1P: length 6.7
  TOP w0.305: U1.4 38.96,9.4 38.99,9.43 42.23,9.43 43.27,8.39 43.93,8.39 C4.2
UNNAMED_4_ADF7242_I75_RFIO2N: length 6.7
  TOP w0.305: U1.7 38.96,10.9 38.99,10.87 42.23,10.87 43.27,11.91 43.92,11.91 C8.2
UNNAMED_4_ADF7242_I75_RFIO2P: length 6.7
  TOP w0.305: C7.2 43.92,11.46 43.46,11.46 42.42,10.41 38.99,10.41 38.98,10.4 U1.6
UNNAMED_4_ADF7242_I75_TRCLKCKOG: length 4.3
  TOP w0.254: U1.19 31.23,10.4 R9.1
UNNAMED_4_ADF7242_I75_XOSC26N: length 7.1
  TOP w0.203: C20.2 33.06,16.98 Y1.3 35.56,16.38 U1.13
UNNAMED_4_ADF7242_I75_XOSC26P: length 9
  TOP w0.203: U1.12 36.06,17.65 37,18.58 Y1.1 37.21,18.54 C10.2
UNNAMED_4_ADF7242_I75_XOSC32KNA: length 7.5
  TOP w0.203: U1.29 36.06,3.03 Y2.1 38.23,2.03 C26.2
UNNAMED_4_ADF7242_I75_XOSC32KPG: length 7.5
  TOP w0.203: U1.28 35.56,3.03 34.57,2.03 33.4,2.03 C27.2
UNNAMED_4_CAP_I13_N1: length 1.6
  TOP w0.254: U2.3 47.05,12.09
  TOP w0.305: 47.05,12.09 45.82,12.09 C8.1
UNNAMED_4_CAP_I97_N1: length 1.6
  TOP w0.254: U2.4 47.05,11.28
  TOP w0.305: C7.1 45.82,11.28 47.05,11.28
UNNAMED_4_CAP_I98_N1: length 1.6
  TOP w0.305: U3.3 45.82,9.04 C6.1
UNNAMED_4_CAP_I99_N1: length 1.6
  TOP w0.305: C4.1 45.82,8.23 U3.4
UNNAMED_4_CAP_I134_N2: length 4.6
  TOP w0.762: 52.76,13.65 C19.2 51.62,12.51 arc(51.19,12.23) 50.69,12.13 48.77,12.13
UNNAMED_4_CAP_I146_N2: length 4.6
  TOP w0.762: 52.76,7.56 C29.2 51.62,8.69 arc(51.19,8.98) 50.69,9.08 48.77,9.08
UNNAMED_4_CN12PV3_I76_P9: length 5.4
  TOP w0.254: P1.9 5.67,12.83 R6.1

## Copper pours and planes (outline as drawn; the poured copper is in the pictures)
DGND on TOP: 2.29,0.64 2.29,2.29 0.64,2.29 0.64,18.01 1.97,18.35 2.31,19.68 47.37,19.68 47.37,19.69 52.2,19.69 52.2,16.51 53.4,15.3 51.94,13.84 51.94,13.72 52.83,12.83 52.96,12.83 54.42,14.29 57.28,11.43 57.28,9.91 54.36,6.98 52.58,8.76 52.32,8.76 51.56,9.53 51.44,9.4 51.44,9.02 50.86,8.45 53.34,5.97 52.2,4.83 52.2,0.64 12.83,0.64 12.83,0.64 ; 3 cut-outs
DGND on BOTTOM: 12.83,0.64 12.83,2.29 0.64,2.29 0.64,19.68 52.2,19.68 52.2,16.51 57.28,11.43 57.28,9.91 52.2,4.83 52.2,0.64 ; 4 cut-outs
DGND on L2_GND, L3_GND: 0.64,0.64 0.64,19.68 52.2,19.68 52.2,16.51 57.28,11.43 57.28,9.91 52.2,4.83 52.2,0.64
DVDD on TOP: 10.16,5.33 10.16,1.52 3.94,1.52 3.94,4.32 4.06,4.45 7.62,4.45 8.51,5.33
RFVDD on TOP: 22.86,2.79 22.86,4.06 22.35,4.57 10.92,4.57 10.92,6.1 22.35,6.1 23.37,5.08 23.37,2.79
RFVDD on BOTTOM: 22.86,4.06 28.45,4.06 29.27,3.24 29.27,2.79 22.86,2.79
UNNAMED_4_CAP_I134_N2 on TOP: 52.77,13.08 53.34,13.65 53.34,13.72 52.83,14.22 52.77,14.22 52.2,13.65
UNNAMED_4_CAP_I134_N2 on TOP: 48.01,11.81 48.01,12.37 48.08,12.47 48.2,12.51 49.4,12.51 49.4,11.75 48.7,11.75 48.63,11.76 48.58,11.81
UNNAMED_4_CAP_I144_N2 on TOP: 55.24,17.27 56.39,16.13 55.75,15.49 55.5,15.75 53.72,13.97 53.09,14.61 54.86,16.38 54.61,16.64
UNNAMED_4_CAP_I145_N2 on TOP: 56.39,5.08 55.24,3.94 54.61,4.57 54.86,4.83 53.09,6.6 53.72,7.24 55.5,5.46 55.75,5.71
UNNAMED_4_CAP_I146_N2 on TOP: 48.01,8.76 48.01,9.32 48.08,9.42 48.2,9.46 49.4,9.46 49.4,8.7 48.7,8.7 48.63,8.72 48.58,8.76 48.52,8.76 48.51,8.75 48.48,8.76 48.45,8.76
UNNAMED_4_CAP_I146_N2 on TOP: 52.77,8.13 53.34,7.56 53.34,7.49 52.83,6.98 52.77,6.98 52.2,7.56

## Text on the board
BOTTOM: 08-039960 REV.A
Ref Des/Silkscreen Top: SPORT PMOD | SPI PMOD
DIMENSION: (REF)
User.15: 16.93 MILS | PER IPC-4552 LATEST REVISION | ENIG (Electroless Nickel/Immersion Gold) | IMPEDANCE CONTROLLED = 30 MILS | CHARACTERISTIC IMPEDANCE = 50 OHMS | ARTWORK LINE WIDTH FOR | 50 OHMS | ROHS COMPLIANCE NOTE: | THE EU RoHS DIRECTIVE 2002/95/EC | HOMOGENOUS MATERIALS IN THIS BOARD SHALL BE COMPLIANT
User.45: EVAL-ADF7242-PMDZ REV.A | FIGURE | SIZE | 10.0 | 45.0 | PLATED | FINISHED HOLES IN MILS | ALL UNITS ARE IN MILS | QTY | 314 | 21 | TOLERANCE/NOTES
